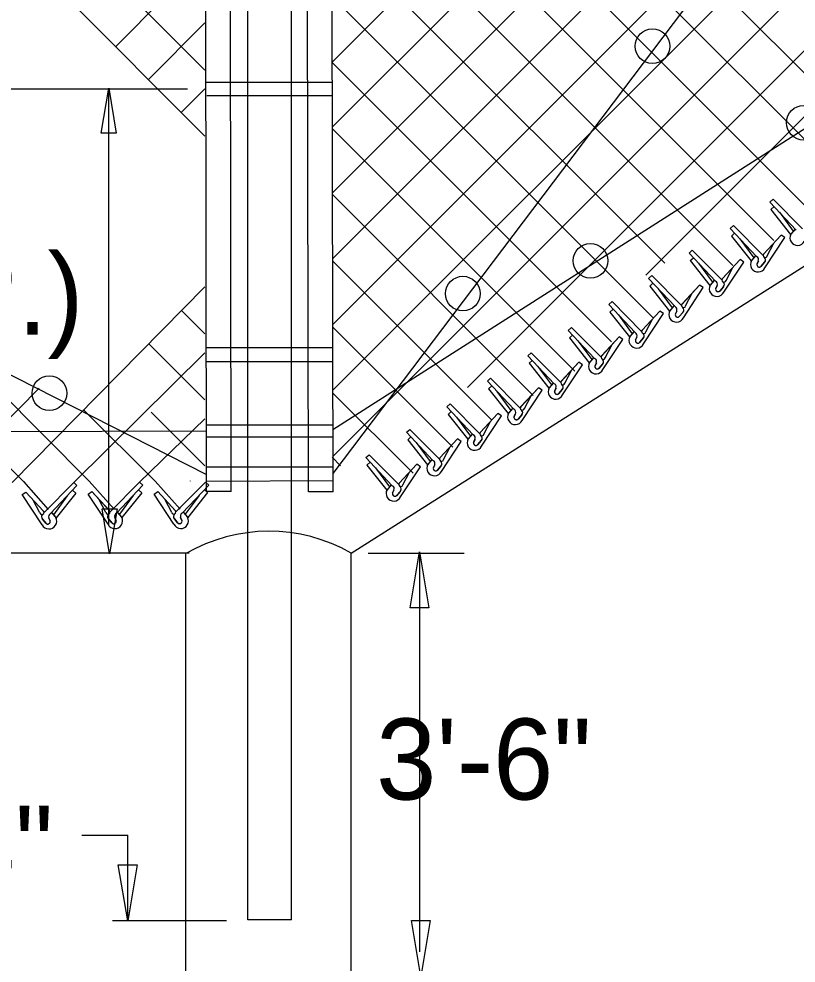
# Model space of a CAD drawing. Extents: x 0 to 1270, y 0 to 830.
# Drawn here: x 613.6 to 661.1, y 574.4 to 632.1 of the extents above; entities that cross this region are included whole.
import ezdxf

# ---------------------------------------------------------------- set-up
doc = ezdxf.new("R2010")
doc.units = 0
for name, color, linetype in [('CT_Dimensions', 7, 'Continuous'), ('sb_Chainlink Fence', 7, 'Continuous'), ('sb_Earth', 7, 'Continuous'), ('sb_Existing Concrete', 7, 'Continuous'), ('sb_Existing Structural Steel', 7, 'Continuous')]:
    doc.layers.add(name, color=color, linetype=linetype)

msp = doc.modelspace()

# ---------------------------------------------------------------- linework, layer by layer
at = {"layer": 'CT_Dimensions'}
for p, q in [((612.93, 627.88), (623.885, 627.88)), ((619.069, 601.19), (619.069, 627.856)), ((634.916, 599.502), (640.788, 599.502)), ((638.075, 575.132), (638.075, 599.488)), ((617.417, 582.265), (620.222, 582.265)), ((620.222, 577.039), (620.222, 582.265)), ((619.3, 577.053), (626.252, 577.053))]:
    msp.add_line(p, q, dxfattribs=at)
for points in [[(618.608, 625.153), (619.066, 627.902), (619.524, 625.153)], [(619.578, 602.208), (619.12, 599.459), (618.662, 602.208)], [(637.494, 596.155), (638.066, 599.584), (638.638, 596.155)], [(620.793, 580.459), (620.222, 577.03), (619.65, 580.459)], [(638.711, 577.047), (638.139, 573.617), (637.568, 577.047)]]:
    msp.add_lwpolyline(points, close=True, dxfattribs=at)
at = {"layer": 'sb_Chainlink Fence'}
for p, q in [((632.746, 613.457), (771.167, 751.878)), ((632.741, 617.482), (759.121, 743.863)), ((632.735, 621.508), (749.785, 738.558)), ((632.73, 625.533), (738.073, 730.876)), ((632.726, 629.509), (730.399, 727.183)), ((632.751, 609.432), (716.137, 692.817)), ((632.756, 605.407), (716.172, 688.823)), ((640.993, 609.613), (716.208, 684.828)), ((596.762, 657.236), (624.936, 629.008)), ((632.689, 657.725), (667.185, 623.228)), ((592.942, 657.072), (624.935, 624.978)), ((632.694, 653.689), (664.548, 621.835)), ((632.699, 649.654), (662.222, 620.131)), ((632.704, 645.618), (659.721, 618.601)), ((632.71, 641.582), (657.22, 617.071)), ((632.715, 637.547), (653.048, 617.214)), ((619.505, 630.467), (624.938, 635.932)), ((632.72, 633.511), (652.367, 613.864)), ((651.902, 616.491), (668.943, 633.532)), ((621.504, 628.442), (624.937, 631.9)), ((632.725, 629.475), (649.788, 612.412)), ((623.496, 626.414), (624.936, 627.869)), ((632.73, 625.439), (647.56, 610.61)), ((632.736, 621.404), (645, 609.139)), ((659.47, 620.954), (659.668, 621.133)), ((661.08, 619.239), (659.47, 620.954)), ((661.479, 619.31), (659.668, 621.133)), ((659.536, 620.491), (659.734, 620.67)), ((659.536, 620.491), (660.741, 618.972)), ((660.056, 620.324), (660.903, 619.168)), ((657.055, 619.336), (657.253, 619.515)), ((658.666, 617.621), (657.055, 619.336)), ((659.065, 617.691), (657.253, 619.515)), ((661.01, 619.282), (660.764, 618.993)), ((661.013, 619.287), (660.765, 618.994)), ((657.122, 618.872), (657.32, 619.052)), ((657.122, 618.872), (658.327, 617.354)), ((657.641, 618.706), (658.488, 617.55)), ((660.174, 618.934), (659.087, 617.766)), ((660.174, 618.934), (659.094, 617.773)), ((659.176, 616.938), (660.396, 618.781)), ((660.396, 618.781), (660.174, 618.934)), ((660.747, 618.96), (660.731, 618.923)), ((660.765, 618.994), (660.747, 618.96)), ((654.535, 617.837), (654.733, 618.016)), ((656.545, 616.193), (654.733, 618.016)), ((659.316, 617.665), (659.722, 618.441)), ((656.146, 616.122), (654.535, 617.837)), ((654.602, 617.374), (654.8, 617.553)), ((657.654, 617.435), (656.567, 616.267)), ((657.654, 617.435), (656.574, 616.274)), ((657.876, 617.282), (657.654, 617.435)), ((658.595, 617.664), (658.349, 617.374)), ((658.598, 617.668), (658.351, 617.375)), ((632.741, 617.368), (642.441, 607.668)), ((654.602, 617.374), (655.806, 615.855)), ((655.121, 617.207), (655.968, 616.051)), ((656.656, 615.439), (657.876, 617.282)), ((656.796, 616.167), (657.202, 616.942)), ((658.332, 617.341), (658.317, 617.305)), ((658.351, 617.375), (658.332, 617.341)), ((658.69, 617.174), (658.772, 617.351)), ((658.771, 617.344), (658.69, 617.178)), ((659.153, 617.272), (658.93, 617.009)), ((658.95, 617.031), (659.153, 617.272)), ((652.066, 616.274), (652.264, 616.454)), ((653.677, 614.559), (652.066, 616.274)), ((654.076, 614.63), (652.264, 616.454)), ((613.154, 603.824), (624.933, 615.774)), ((652.133, 615.811), (652.331, 615.991)), ((652.133, 615.811), (653.337, 614.293)), ((655.184, 615.873), (654.098, 614.705)), ((655.184, 615.873), (654.105, 614.712)), ((654.187, 613.877), (655.407, 615.72)), ((655.407, 615.72), (655.184, 615.873)), ((655.812, 615.843), (655.797, 615.806)), ((655.83, 615.877), (655.812, 615.843)), ((656.075, 616.165), (655.829, 615.876)), ((656.078, 616.17), (655.83, 615.877)), ((656.17, 615.675), (656.251, 615.852)), ((656.251, 615.846), (656.17, 615.679)), ((656.633, 615.774), (656.41, 615.51)), ((656.43, 615.532), (656.633, 615.774)), ((652.652, 615.645), (653.499, 614.489)), ((654.327, 614.604), (654.733, 615.38)), ((649.629, 614.688), (649.828, 614.867)), ((651.24, 612.973), (649.629, 614.688)), ((651.639, 613.044), (649.828, 614.867)), ((653.606, 614.603), (653.36, 614.313)), ((653.609, 614.607), (653.361, 614.314)), ((623.502, 614.323), (624.932, 612.89)), ((649.696, 614.225), (649.894, 614.404)), ((649.696, 614.225), (650.901, 612.706)), ((650.215, 614.058), (651.063, 612.902)), ((652.748, 614.286), (651.662, 613.118)), ((652.748, 614.286), (651.669, 613.125)), ((651.751, 612.29), (652.971, 614.133)), ((652.971, 614.133), (652.748, 614.286)), ((653.343, 614.28), (653.328, 614.244)), ((653.361, 614.314), (653.343, 614.28)), ((653.7, 614.113), (653.782, 614.29)), ((653.782, 614.283), (653.701, 614.117)), ((654.164, 614.211), (653.941, 613.948)), ((653.961, 613.97), (654.164, 614.211)), ((651.89, 613.018), (652.297, 613.793)), ((632.746, 613.332), (640.095, 605.983)), ((647.153, 613.111), (647.351, 613.29)), ((648.764, 611.396), (647.153, 613.111)), ((647.219, 612.648), (647.418, 612.827)), ((649.163, 611.467), (647.351, 613.29)), ((651.17, 613.016), (650.924, 612.727)), ((651.173, 613.021), (650.925, 612.728)), ((621.505, 612.293), (624.931, 608.86)), ((647.219, 612.648), (648.424, 611.129)), ((647.739, 612.481), (648.586, 611.325)), ((650.271, 612.709), (649.185, 611.541)), ((650.271, 612.709), (649.192, 611.548)), ((649.274, 610.713), (650.494, 612.556)), ((649.413, 611.441), (649.82, 612.216)), ((650.494, 612.556), (650.271, 612.709)), ((650.907, 612.694), (650.891, 612.657)), ((650.925, 612.728), (650.907, 612.694)), ((651.264, 612.526), (651.346, 612.703)), ((651.346, 612.697), (651.264, 612.53)), ((651.727, 612.625), (651.504, 612.361)), ((651.525, 612.383), (651.727, 612.625)), ((609.899, 611.909), (617.877, 603.896)), ((616.921, 603.81), (624.932, 611.743)), ((644.686, 611.561), (644.884, 611.74)), ((646.696, 609.917), (644.884, 611.74)), ((646.297, 609.846), (644.686, 611.561)), ((644.753, 611.098), (644.951, 611.277)), ((644.753, 611.098), (645.958, 609.579)), ((647.805, 611.159), (646.719, 609.991)), ((647.805, 611.159), (646.726, 609.998)), ((648.028, 611.006), (647.805, 611.159)), ((648.43, 611.117), (648.414, 611.08)), ((648.448, 611.151), (648.43, 611.117)), ((648.693, 611.439), (648.447, 611.15)), ((648.696, 611.444), (648.448, 611.151)), ((648.787, 610.949), (648.869, 611.126)), ((648.869, 611.12), (648.787, 610.953)), ((645.272, 610.931), (646.12, 609.775)), ((646.808, 609.163), (648.028, 611.006)), ((646.947, 609.891), (647.354, 610.666)), ((649.25, 611.048), (649.028, 610.784)), ((649.048, 610.806), (649.25, 611.048)), ((607.463, 610.294), (613.882, 603.846)), ((642.208, 610.008), (642.406, 610.187)), ((643.819, 608.293), (642.208, 610.008)), ((644.217, 608.364), (642.406, 610.187)), ((609.113, 603.824), (614.812, 609.581)), ((642.274, 609.545), (642.472, 609.724)), ((642.274, 609.545), (643.479, 608.026)), ((642.794, 609.378), (643.641, 608.222)), ((645.326, 609.606), (644.24, 608.439)), ((645.326, 609.606), (644.247, 608.445)), ((644.329, 607.61), (645.549, 609.454)), ((645.549, 609.454), (645.326, 609.606)), ((645.964, 609.567), (645.948, 609.53)), ((645.982, 609.601), (645.964, 609.567)), ((646.226, 609.889), (645.981, 609.6)), ((646.23, 609.894), (645.982, 609.601)), ((646.321, 609.399), (646.403, 609.576)), ((646.403, 609.57), (646.321, 609.403)), ((646.784, 609.498), (646.561, 609.234)), ((646.582, 609.256), (646.784, 609.498)), ((632.751, 609.296), (637.672, 604.376)), ((644.468, 608.338), (644.875, 609.113)), ((617.525, 608.259), (621.904, 603.899)), ((639.736, 608.437), (639.934, 608.616)), ((641.347, 606.722), (639.736, 608.437)), ((641.746, 606.793), (639.934, 608.616)), ((643.748, 608.336), (643.502, 608.047)), ((643.751, 608.341), (643.503, 608.048)), ((620.949, 603.832), (624.931, 607.711)), ((621.647, 608.115), (624.93, 604.831)), ((639.803, 607.974), (640.001, 608.153)), ((639.803, 607.974), (641.007, 606.456)), ((640.322, 607.808), (641.169, 606.652)), ((642.854, 608.035), (641.768, 606.868)), ((642.854, 608.035), (641.775, 606.875)), ((641.857, 606.04), (643.077, 607.883)), ((643.077, 607.883), (642.854, 608.035)), ((643.485, 608.014), (643.469, 607.978)), ((643.503, 608.048), (643.485, 608.014)), ((643.842, 607.846), (643.924, 608.023)), ((643.924, 608.017), (643.842, 607.85)), ((644.305, 607.945), (644.083, 607.681)), ((644.103, 607.703), (644.305, 607.945)), ((637.273, 606.882), (637.471, 607.062)), ((639.283, 605.238), (637.471, 607.062)), ((641.996, 606.767), (642.403, 607.543)), ((638.884, 605.167), (637.273, 606.882)), ((637.34, 606.419), (637.538, 606.598)), ((640.392, 606.481), (639.305, 605.313)), ((640.392, 606.481), (639.312, 605.32)), ((640.614, 606.328), (640.392, 606.481)), ((641.013, 606.443), (640.998, 606.407)), ((641.031, 606.477), (641.013, 606.443)), ((641.276, 606.766), (641.03, 606.476)), ((641.279, 606.77), (641.031, 606.477)), ((641.37, 606.275), (641.452, 606.452)), ((641.452, 606.446), (641.371, 606.279)), ((637.34, 606.419), (638.545, 604.901)), ((637.859, 606.253), (638.706, 605.097)), ((639.394, 604.485), (640.614, 606.328)), ((639.534, 605.212), (639.94, 605.988)), ((641.834, 606.374), (641.611, 606.111)), ((641.631, 606.132), (641.834, 606.374)), ((634.783, 605.335), (634.981, 605.514)), ((636.394, 603.62), (634.783, 605.335)), ((636.793, 603.691), (634.981, 605.514)), ((634.85, 604.872), (635.048, 605.051)), ((634.85, 604.872), (636.055, 603.354)), ((635.369, 604.706), (636.216, 603.55)), ((637.902, 604.933), (636.815, 603.766)), ((637.902, 604.933), (636.822, 603.773)), ((636.904, 602.938), (638.124, 604.781)), ((638.124, 604.781), (637.902, 604.933)), ((638.55, 604.888), (638.535, 604.852)), ((638.569, 604.922), (638.55, 604.888)), ((638.813, 605.211), (638.567, 604.921)), ((638.816, 605.215), (638.569, 604.922)), ((638.908, 604.721), (638.99, 604.898)), ((638.989, 604.891), (638.908, 604.725)), ((639.371, 604.819), (639.148, 604.556)), ((639.168, 604.577), (639.371, 604.819)), ((637.044, 603.665), (637.45, 604.441)), ((613.849, 603.873), (615.367, 602.165)), ((615.107, 601.989), (616.921, 603.81)), ((615.506, 601.917), (617.119, 603.631)), ((617.119, 603.631), (616.921, 603.81)), ((617.877, 603.896), (619.395, 602.187)), ((619.136, 602.011), (620.949, 603.832)), ((619.535, 601.94), (621.147, 603.653)), ((621.147, 603.653), (620.949, 603.832)), ((621.904, 603.899), (623.421, 602.19)), ((623.162, 602.014), (624.976, 603.835)), ((623.561, 601.943), (625.174, 603.656)), ((624.054, 603.901), (624.065, 603.908)), ((636.323, 603.664), (636.077, 603.374)), ((636.326, 603.668), (636.079, 603.375)), ((613.777, 603.08), (614, 603.232)), ((614.995, 601.235), (613.777, 603.08)), ((614, 603.232), (615.078, 602.07)), ((614, 603.232), (615.085, 602.063)), ((616.532, 603.002), (615.684, 601.847)), ((617.052, 603.168), (615.845, 601.65)), ((617.052, 603.168), (616.854, 603.347)), ((617.805, 603.102), (618.028, 603.254)), ((619.024, 601.258), (617.805, 603.102)), ((618.028, 603.254), (619.106, 602.093)), ((618.028, 603.254), (619.113, 602.086)), ((620.561, 603.024), (619.712, 601.869)), ((621.08, 603.19), (619.874, 601.673)), ((621.08, 603.19), (620.882, 603.369)), ((621.832, 603.105), (622.055, 603.257)), ((623.05, 601.26), (621.832, 603.105)), ((622.055, 603.257), (623.133, 602.095)), ((622.055, 603.257), (623.14, 602.089)), ((624.587, 603.027), (623.738, 601.872)), ((625.107, 603.193), (623.9, 601.675)), ((636.06, 603.341), (636.045, 603.305)), ((636.079, 603.375), (636.06, 603.341)), ((636.418, 603.173), (636.5, 603.351)), ((636.499, 603.344), (636.418, 603.178)), ((636.881, 603.272), (636.658, 603.009)), ((636.679, 603.03), (636.881, 603.272)), ((614.857, 601.963), (614.451, 602.739)), ((618.885, 601.985), (618.479, 602.761)), ((622.911, 601.988), (622.505, 602.764)), ((615.574, 601.965), (615.821, 601.672)), ((615.577, 601.961), (615.823, 601.671)), ((619.602, 601.987), (619.85, 601.694)), ((619.605, 601.983), (619.851, 601.693)), ((623.629, 601.99), (623.876, 601.697)), ((623.632, 601.986), (623.877, 601.696)), ((615.221, 601.328), (615.019, 601.57)), ((615.019, 601.57), (615.242, 601.306)), ((615.482, 601.47), (615.4, 601.648)), ((615.401, 601.641), (615.482, 601.474)), ((615.821, 601.672), (615.84, 601.638)), ((615.84, 601.638), (615.855, 601.601)), ((619.249, 601.35), (619.047, 601.592)), ((619.047, 601.592), (619.27, 601.328)), ((619.51, 601.493), (619.429, 601.67)), ((619.429, 601.664), (619.51, 601.497)), ((619.85, 601.694), (619.868, 601.66)), ((619.868, 601.66), (619.883, 601.624)), ((623.276, 601.353), (623.074, 601.595)), ((623.074, 601.595), (623.296, 601.331)), ((623.537, 601.496), (623.455, 601.673)), ((623.455, 601.667), (623.537, 601.5)), ((623.876, 601.697), (623.894, 601.663)), ((623.894, 601.663), (623.91, 601.627))]:
    msp.add_line(p, q, dxfattribs=at)
for centre, radius, start, end in [((661.172, 618.764), 0.468, 150.71281, 333.61946), ((658.578, 617.431), 0.209, 336.42297, 65.09751), ((659.19, 617.688), 0.128, 138.96114, 350.00924), ((659.018, 617.414), 0.195, 313.60687, 52.17404), ((659.023, 617.414), 0.192, 320.14134, 52.94493), ((658.757, 617.146), 0.468, 150.71281, 333.61946), ((658.834, 617.127), 0.152, 160.67404, 309.15708), ((658.834, 617.128), 0.152, 162.45444, 320.07649), ((656.67, 616.189), 0.128, 138.96114, 350.00924), ((656.237, 615.647), 0.468, 150.71281, 333.61946), ((656.058, 615.932), 0.209, 336.42297, 65.09751), ((656.314, 615.629), 0.152, 160.67404, 309.15708), ((656.314, 615.629), 0.152, 162.45444, 320.07649), ((656.498, 615.915), 0.195, 313.60687, 52.17404), ((656.503, 615.915), 0.192, 320.14134, 52.94493), ((653.589, 614.37), 0.209, 336.42297, 65.09751), ((654.201, 614.627), 0.128, 138.96114, 350.00924), ((653.768, 614.085), 0.468, 150.71281, 333.61946), ((653.845, 614.066), 0.152, 160.67404, 309.15708), ((653.845, 614.067), 0.152, 162.45444, 320.07649), ((654.029, 614.353), 0.195, 313.60687, 52.17404), ((654.034, 614.353), 0.192, 320.14134, 52.94493), ((651.152, 612.783), 0.209, 336.42297, 65.09751), ((651.764, 613.04), 0.128, 138.96114, 350.00924), ((651.592, 612.766), 0.195, 313.60687, 52.17404), ((651.598, 612.766), 0.192, 320.14134, 52.94493), ((651.332, 612.498), 0.468, 150.71281, 333.61946), ((651.408, 612.48), 0.152, 160.67404, 309.15708), ((651.409, 612.48), 0.152, 162.45444, 320.07649), ((648.855, 610.921), 0.468, 150.71281, 333.61946), ((648.675, 611.206), 0.209, 336.42297, 65.09751), ((649.287, 611.463), 0.128, 138.96114, 350.00924), ((649.116, 611.189), 0.195, 313.60687, 52.17404), ((649.121, 611.189), 0.192, 320.14134, 52.94493), ((648.931, 610.903), 0.152, 160.67404, 309.15708), ((648.932, 610.903), 0.152, 162.45444, 320.07649), ((646.821, 609.913), 0.128, 138.96114, 350.00924), ((646.389, 609.371), 0.468, 150.71281, 333.61946), ((646.209, 609.656), 0.209, 336.42297, 65.09751), ((646.465, 609.353), 0.152, 160.67404, 309.15708), ((646.466, 609.353), 0.152, 162.45444, 320.07649), ((646.649, 609.639), 0.195, 313.60687, 52.17404), ((646.655, 609.639), 0.192, 320.14134, 52.94493), ((643.73, 608.103), 0.209, 336.42297, 65.09751), ((644.342, 608.36), 0.128, 138.96114, 350.00924), ((644.171, 608.086), 0.195, 313.60687, 52.17404), ((644.176, 608.087), 0.192, 320.14134, 52.94493), ((643.91, 607.818), 0.468, 150.71281, 333.61946), ((643.986, 607.8), 0.152, 160.67404, 309.15708), ((643.987, 607.8), 0.152, 162.45444, 320.07649), ((641.438, 606.247), 0.468, 150.71281, 333.61946), ((641.259, 606.532), 0.209, 336.42297, 65.09751), ((641.871, 606.789), 0.128, 138.96114, 350.00924), ((641.699, 606.516), 0.195, 313.60687, 52.17404), ((641.704, 606.516), 0.192, 320.14134, 52.94493), ((641.514, 606.229), 0.152, 160.67404, 309.15708), ((641.515, 606.23), 0.152, 162.45444, 320.07649), ((639.408, 605.235), 0.128, 138.96114, 350.00924), ((638.975, 604.693), 0.468, 150.71281, 333.61946), ((638.796, 604.977), 0.209, 336.42297, 65.09751), ((639.052, 604.674), 0.152, 160.67404, 309.15708), ((639.052, 604.675), 0.152, 162.45444, 320.07649), ((639.236, 604.961), 0.195, 313.60687, 52.17404), ((639.241, 604.961), 0.192, 320.14134, 52.94493), ((636.306, 603.43), 0.209, 336.42297, 65.09751), ((636.918, 603.688), 0.128, 138.96114, 350.00924), ((636.746, 603.414), 0.195, 313.60687, 52.17404), ((636.751, 603.414), 0.192, 320.14134, 52.94493), ((636.485, 603.146), 0.468, 150.71281, 333.61946), ((636.562, 603.127), 0.152, 160.67404, 309.15708), ((636.562, 603.128), 0.152, 162.45444, 320.07649), ((614.982, 601.985), 0.128, 189.93044, 40.97854), ((615.149, 601.711), 0.192, 126.99475, 219.79834), ((615.154, 601.711), 0.195, 127.76564, 226.33281), ((615.594, 601.727), 0.209, 114.84217, 203.51672), ((619.011, 602.007), 0.128, 189.93044, 40.97854), ((619.177, 601.734), 0.192, 126.99475, 219.79834), ((619.182, 601.733), 0.195, 127.76564, 226.33281), ((619.623, 601.75), 0.209, 114.84217, 203.51672), ((623.037, 602.01), 0.128, 189.93044, 40.97854), ((623.204, 601.736), 0.192, 126.99475, 219.79834), ((623.209, 601.736), 0.195, 127.76564, 226.33281), ((623.649, 601.752), 0.209, 114.84217, 203.51672), ((615.414, 601.443), 0.468, 206.32022, 29.22687), ((615.337, 601.425), 0.152, 219.86319, 17.48524), ((615.338, 601.424), 0.152, 230.7826, 19.26564), ((619.443, 601.465), 0.468, 206.32022, 29.22687), ((619.366, 601.447), 0.152, 219.86319, 17.48524), ((619.366, 601.447), 0.152, 230.7826, 19.26564), ((623.469, 601.468), 0.468, 206.32022, 29.22687), ((623.392, 601.45), 0.152, 219.86319, 17.48524), ((623.393, 601.449), 0.152, 230.7826, 19.26564)]:
    msp.add_arc(centre, radius, start, end, dxfattribs=at)
at = {"layer": 'sb_Earth'}
for p, q in [((633.881, 599.502), (772.831, 687.523)), ((416.568, 599.501), (623.976, 599.514))]:
    msp.add_line(p, q, dxfattribs=at)
at = {"layer": 'sb_Existing Concrete'}
for p, q in [((623.772, 573.689), (623.776, 599.471)), ((633.877, 573.689), (633.881, 599.502))]:
    msp.add_line(p, q, dxfattribs=at)
msp.add_arc((628.856, 590.689), 10.145, 60.31244, 120.04705, dxfattribs=at)
at = {"layer": 'sb_Existing Structural Steel'}
for p, q in [((632.766, 607.059), (768.798, 693.845)), ((627.56, 600.749), (627.56, 664.694)), ((630.232, 600.74), (630.232, 664.694)), ((631.265, 603.243), (631.175, 661.767)), ((632.773, 603.243), (632.683, 661.761)), ((625.047, 603.256), (624.959, 660.742)), ((626.555, 603.256), (626.467, 660.742)), ((663.417, 644.911), (632.755, 604.354)), ((632.732, 628.25), (625.036, 628.25)), ((632.762, 627.443), (625.064, 627.443)), ((610.268, 611.809), (625.037, 604.303)), ((632.722, 612.042), (625.051, 612.043)), ((632.78, 611.197), (625.032, 611.187)), ((632.769, 607.318), (625.037, 607.318)), ((414.308, 606.611), (625.03, 606.961)), ((632.753, 606.588), (625.057, 606.588)), ((632.728, 605.357), (633.229, 604.826)), ((632.754, 604.746), (625.057, 604.746)), ((625.174, 603.656), (624.976, 603.835)), ((632.786, 603.917), (625.057, 603.874)), ((625.107, 603.193), (624.909, 603.372)), ((626.555, 603.256), (625.047, 603.256)), ((632.773, 603.243), (631.265, 603.243)), ((627.56, 577.085), (627.56, 600.746)), ((630.232, 577.085), (630.232, 600.746)), ((630.232, 577.085), (627.56, 577.085))]:
    msp.add_line(p, q, dxfattribs=at)
for centre in [(652.297, 630.473), (661.548, 625.801), (648.511, 617.363), (640.709, 615.354), (615.434, 609.269)]:
    msp.add_circle(centre, 1.06, dxfattribs=at)

# ---------------------------------------------------------------- texts
at = {"layer": 'CT_Dimensions'}
for s, p in [('(TYP.)', (598.403, 612.85)), (' 3\'-6"', (633.567, 584.44)), ('4"', (609.652, 579.117))]:
    msp.add_text(s, height=4.95, rotation=360, dxfattribs=at).set_placement(p)

doc.saveas('drawing.dxf')
